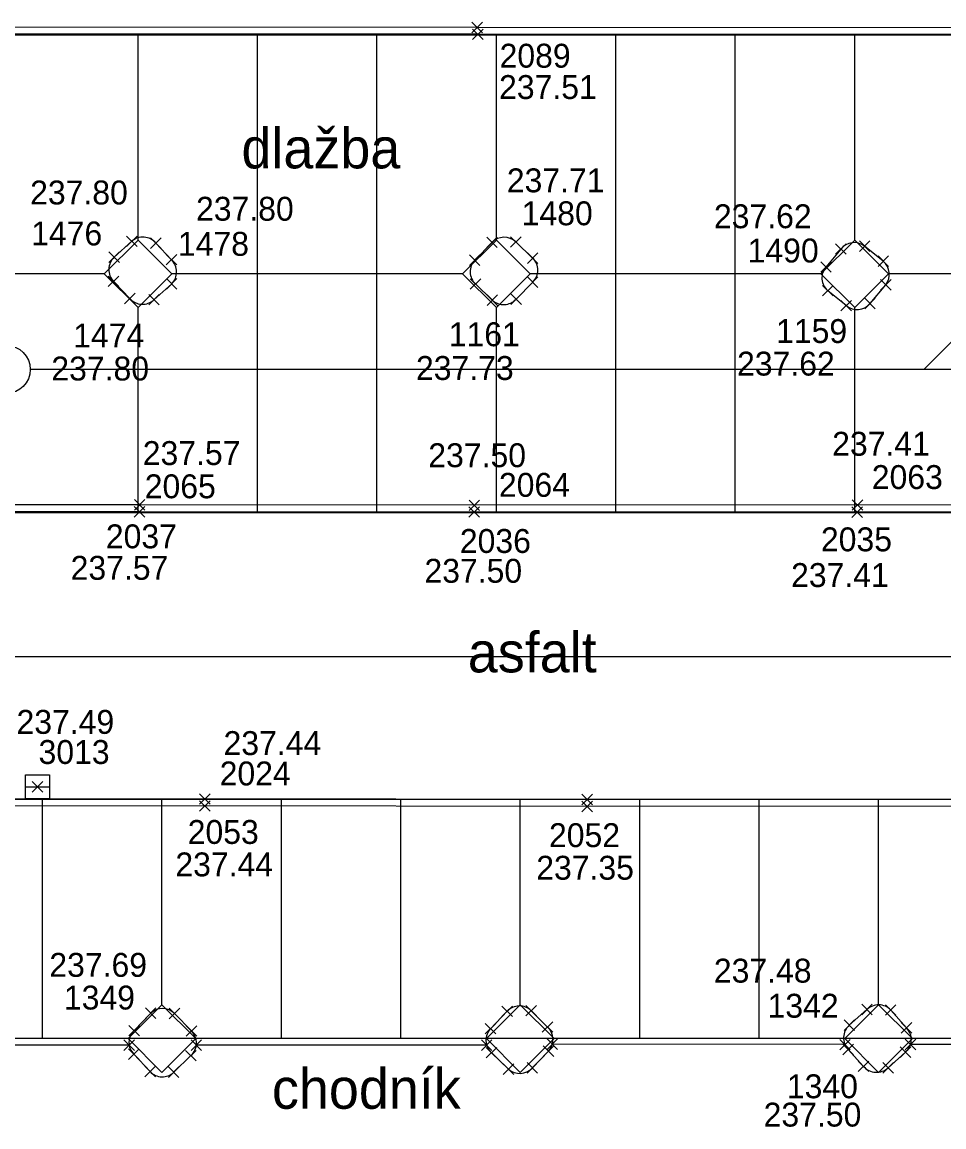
# Model space of a CAD drawing. Extents: x -264165 to -263733, y -1242319 to -1242245.
# Drawn here: x -263870.5 to -263851.2, y -1242299.83 to -1242276.71 of the extents above; entities that cross this region are included whole.
import ezdxf

# ---------------------------------------------------------------- set-up
doc = ezdxf.new("R2010")
doc.units = 0
for name, color, linetype in [('KFA_BOD_CISLO', 7, 'Continuous'), ('KFA_BOD_SYMBOL', 7, 'Continuous'), ('KFA_BOD_VYSKA', 7, 'Continuous'), ('KFA_SO_20-2_OBRUBNIKY_DOLNA_HRANA', 7, 'Continuous'), ('KFA_SO_20-2_OBRUBNIKY_HORNA_HRANA', 7, 'Continuous'), ('KFA_UV_BOD_CISLO', 7, 'Continuous'), ('KFA_UV_BOD_SYMBOL', 7, 'Continuous'), ('KFA_UV_BOD_VYSKA', 7, 'Continuous'), ('POPIS', 7, 'Continuous'), ('PROJEKT_OBRUBNIKY_KOMUNIKACIE', 7, 'Continuous'), ('PROJEKT_TDZ_VODOROVNE', 7, 'Continuous'), ('SITUACIA_DSP_2D', 7, 'Continuous'), ('ULICNA_VPUST_POKLOP', 7, 'Continuous')]:
    doc.layers.add(name, color=color, linetype=linetype)

msp = doc.modelspace()

# ---------------------------------------------------------------- linework, layer by layer
at = {"layer": 'KFA_BOD_SYMBOL'}
for p, q in [((-263861.079, -1242276.936), (-263860.858, -1242276.715)), ((-263860.858, -1242276.936), (-263861.079, -1242276.715)), ((-263861.068, -1242277.079), (-263860.847, -1242276.859)), ((-263860.847, -1242277.079), (-263861.068, -1242276.859)), ((-263868.311, -1242281.411), (-263868.09, -1242281.191)), ((-263868.09, -1242281.411), (-263868.311, -1242281.191)), ((-263860.272, -1242281.426), (-263860.051, -1242281.204)), ((-263860.051, -1242281.426), (-263860.272, -1242281.204)), ((-263867.806, -1242281.448), (-263867.584, -1242281.227)), ((-263867.584, -1242281.448), (-263867.806, -1242281.227)), ((-263860.769, -1242281.434), (-263860.549, -1242281.214)), ((-263860.549, -1242281.434), (-263860.769, -1242281.214)), ((-263853.469, -1242281.573), (-263853.247, -1242281.353)), ((-263853.247, -1242281.573), (-263853.469, -1242281.353)), ((-263852.971, -1242281.514), (-263852.75, -1242281.292)), ((-263852.75, -1242281.514), (-263852.971, -1242281.292)), ((-263868.677, -1242281.742), (-263868.456, -1242281.522)), ((-263868.456, -1242281.742), (-263868.677, -1242281.522)), ((-263867.48, -1242281.796), (-263867.258, -1242281.576)), ((-263867.258, -1242281.796), (-263867.48, -1242281.576)), ((-263861.133, -1242281.806), (-263860.911, -1242281.585)), ((-263860.911, -1242281.806), (-263861.133, -1242281.585)), ((-263859.92, -1242281.762), (-263859.698, -1242281.542)), ((-263859.698, -1242281.762), (-263859.92, -1242281.542)), ((-263852.579, -1242281.829), (-263852.358, -1242281.607)), ((-263852.358, -1242281.829), (-263852.579, -1242281.607)), ((-263853.78, -1242281.95), (-263853.559, -1242281.728)), ((-263853.559, -1242281.95), (-263853.78, -1242281.728)), ((-263868.691, -1242282.249), (-263868.47, -1242282.029)), ((-263868.47, -1242282.249), (-263868.691, -1242282.029)), ((-263867.475, -1242282.302), (-263867.253, -1242282.08)), ((-263867.253, -1242282.302), (-263867.475, -1242282.08)), ((-263861.116, -1242282.303), (-263860.894, -1242282.083)), ((-263860.894, -1242282.303), (-263861.116, -1242282.083)), ((-263859.919, -1242282.265), (-263859.698, -1242282.045)), ((-263859.698, -1242282.265), (-263859.919, -1242282.045)), ((-263852.529, -1242282.323), (-263852.307, -1242282.102)), ((-263852.307, -1242282.323), (-263852.529, -1242282.102)), ((-263853.743, -1242282.444), (-263853.522, -1242282.224)), ((-263853.522, -1242282.444), (-263853.743, -1242282.224)), ((-263868.351, -1242282.61), (-263868.129, -1242282.389)), ((-263868.129, -1242282.61), (-263868.351, -1242282.389)), ((-263867.845, -1242282.633), (-263867.625, -1242282.413)), ((-263867.625, -1242282.633), (-263867.845, -1242282.413)), ((-263860.764, -1242282.641), (-263860.543, -1242282.421)), ((-263860.543, -1242282.641), (-263860.764, -1242282.421)), ((-263860.264, -1242282.622), (-263860.043, -1242282.4)), ((-263860.043, -1242282.622), (-263860.264, -1242282.4)), ((-263853.356, -1242282.758), (-263853.135, -1242282.536)), ((-263853.135, -1242282.758), (-263853.356, -1242282.536)), ((-263852.859, -1242282.713), (-263852.638, -1242282.492)), ((-263852.638, -1242282.713), (-263852.859, -1242282.492)), ((-263868.144, -1242286.927), (-263867.924, -1242286.705)), ((-263867.924, -1242286.927), (-263868.144, -1242286.705)), ((-263861.141, -1242286.936), (-263860.92, -1242286.715)), ((-263860.92, -1242286.936), (-263861.141, -1242286.715)), ((-263853.122, -1242286.928), (-263852.901, -1242286.708)), ((-263852.901, -1242286.928), (-263853.122, -1242286.708)), ((-263868.148, -1242287.07), (-263867.927, -1242286.85)), ((-263867.927, -1242287.07), (-263868.148, -1242286.85)), ((-263861.143, -1242287.076), (-263860.921, -1242286.856)), ((-263860.921, -1242287.076), (-263861.143, -1242286.856)), ((-263853.128, -1242287.079), (-263852.906, -1242286.857)), ((-263852.906, -1242287.079), (-263853.128, -1242286.857)), ((-263866.781, -1242293.079), (-263866.56, -1242292.859)), ((-263866.56, -1242293.079), (-263866.781, -1242292.859)), ((-263858.78, -1242293.089), (-263858.559, -1242292.867)), ((-263858.559, -1242293.089), (-263858.78, -1242292.867)), ((-263866.779, -1242293.225), (-263866.557, -1242293.005)), ((-263866.557, -1242293.225), (-263866.779, -1242293.005)), ((-263858.778, -1242293.235), (-263858.557, -1242293.014)), ((-263858.557, -1242293.235), (-263858.778, -1242293.014)), ((-263867.914, -1242297.561), (-263867.693, -1242297.34)), ((-263867.693, -1242297.561), (-263867.914, -1242297.34)), ((-263867.414, -1242297.569), (-263867.193, -1242297.349)), ((-263867.193, -1242297.569), (-263867.414, -1242297.349)), ((-263860.454, -1242297.522), (-263860.233, -1242297.301)), ((-263860.233, -1242297.522), (-263860.454, -1242297.301)), ((-263859.949, -1242297.509), (-263859.728, -1242297.289)), ((-263859.728, -1242297.509), (-263859.949, -1242297.289)), ((-263852.922, -1242297.487), (-263852.701, -1242297.265)), ((-263852.701, -1242297.487), (-263852.922, -1242297.265)), ((-263852.425, -1242297.495), (-263852.204, -1242297.275)), ((-263852.204, -1242297.495), (-263852.425, -1242297.275)), ((-263853.291, -1242297.813), (-263853.07, -1242297.593)), ((-263853.07, -1242297.813), (-263853.291, -1242297.593)), ((-263868.262, -1242297.927), (-263868.041, -1242297.705)), ((-263868.041, -1242297.927), (-263868.262, -1242297.705)), ((-263867.062, -1242297.934), (-263866.84, -1242297.713)), ((-263866.84, -1242297.934), (-263867.062, -1242297.713)), ((-263860.8, -1242297.886), (-263860.579, -1242297.664)), ((-263860.579, -1242297.886), (-263860.8, -1242297.664)), ((-263859.611, -1242297.85), (-263859.389, -1242297.63)), ((-263859.389, -1242297.85), (-263859.611, -1242297.63)), ((-263852.095, -1242297.87), (-263851.873, -1242297.649)), ((-263851.873, -1242297.87), (-263852.095, -1242297.649)), ((-263868.366, -1242298.228), (-263868.144, -1242298.008)), ((-263868.144, -1242298.228), (-263868.366, -1242298.008)), ((-263866.959, -1242298.231), (-263866.738, -1242298.011)), ((-263866.738, -1242298.231), (-263866.959, -1242298.011)), ((-263860.883, -1242298.228), (-263860.661, -1242298.008)), ((-263860.661, -1242298.228), (-263860.883, -1242298.008)), ((-263859.508, -1242298.208), (-263859.287, -1242297.988)), ((-263859.287, -1242298.208), (-263859.508, -1242297.988)), ((-263853.382, -1242298.218), (-263853.16, -1242297.998)), ((-263853.16, -1242298.218), (-263853.382, -1242297.998)), ((-263852.012, -1242298.218), (-263851.791, -1242297.997)), ((-263851.791, -1242298.218), (-263852.012, -1242297.997)), ((-263868.268, -1242298.417), (-263868.046, -1242298.197)), ((-263868.046, -1242298.417), (-263868.268, -1242298.197)), ((-263867.073, -1242298.45), (-263866.852, -1242298.228)), ((-263866.852, -1242298.45), (-263867.073, -1242298.228)), ((-263860.781, -1242298.387), (-263860.56, -1242298.167)), ((-263860.56, -1242298.387), (-263860.781, -1242298.167)), ((-263859.59, -1242298.356), (-263859.368, -1242298.134)), ((-263859.368, -1242298.356), (-263859.59, -1242298.134)), ((-263853.315, -1242298.319), (-263853.094, -1242298.097)), ((-263853.094, -1242298.319), (-263853.315, -1242298.097)), ((-263852.117, -1242298.377), (-263851.896, -1242298.156)), ((-263851.896, -1242298.377), (-263852.117, -1242298.156)), ((-263860.427, -1242298.732), (-263860.205, -1242298.512)), ((-263860.205, -1242298.732), (-263860.427, -1242298.512)), ((-263859.925, -1242298.707), (-263859.704, -1242298.485)), ((-263859.704, -1242298.707), (-263859.925, -1242298.485)), ((-263852.995, -1242298.674), (-263852.774, -1242298.453)), ((-263852.774, -1242298.674), (-263852.995, -1242298.453)), ((-263852.478, -1242298.703), (-263852.257, -1242298.481)), ((-263852.257, -1242298.703), (-263852.478, -1242298.481)), ((-263867.927, -1242298.784), (-263867.705, -1242298.562)), ((-263867.705, -1242298.784), (-263867.927, -1242298.562)), ((-263867.432, -1242298.798), (-263867.212, -1242298.576)), ((-263867.212, -1242298.798), (-263867.432, -1242298.576))]:
    msp.add_line(p, q, dxfattribs=at)
at = {"layer": 'KFA_SO_20-2_OBRUBNIKY_DOLNA_HRANA'}
for points in [[(-263816.727, -1242276.824), (-263824.896, -1242276.832), (-263841.932, -1242276.838), (-263860.969, -1242276.825), (-263872.991, -1242276.822), (-263881, -1242276.818), (-263897.019, -1242276.831), (-263905.035, -1242276.846), (-263913.057, -1242276.848), (-263917.557, -1242276.899)], [(-263817.074, -1242276.98), (-263824.904, -1242276.976), (-263831.918, -1242276.976), (-263841.931, -1242276.979), (-263850.949, -1242276.976), (-263860.958, -1242276.969), (-263872.991, -1242276.965), (-263880.996, -1242276.964), (-263889.006, -1242276.968), (-263897.017, -1242276.976), (-263905.035, -1242276.99), (-263913.048, -1242276.994), (-263917.092, -1242277.009)], [(-263819.103, -1242286.786), (-263819.439, -1242286.959), (-263828.996, -1242286.962), (-263838.005, -1242286.965), (-263845.009, -1242286.967), (-263853.017, -1242286.968), (-263861.032, -1242286.966), (-263868.037, -1242286.96), (-263877.037, -1242286.952), (-263886.053, -1242286.951), (-263895.068, -1242286.953), (-263904.067, -1242286.955), (-263910.084, -1242286.961), (-263917.346, -1242286.958)], [(-263819.419, -1242286.819), (-263828.995, -1242286.822), (-263838.007, -1242286.821), (-263845.022, -1242286.826), (-263853.012, -1242286.818), (-263861.03, -1242286.825), (-263868.034, -1242286.816), (-263877.043, -1242286.812), (-263886.05, -1242286.81), (-263895.064, -1242286.807), (-263904.07, -1242286.816), (-263910.08, -1242286.821), (-263917.062, -1242286.824)], [(-263817.492, -1242292.982), (-263829.632, -1242292.973), (-263839.651, -1242292.963), (-263849.653, -1242292.97), (-263858.67, -1242292.978), (-263866.671, -1242292.969), (-263877.683, -1242292.971), (-263887.693, -1242292.984), (-263898.705, -1242293.002), (-263909.705, -1242293.003), (-263917.41, -1242292.997)], [(-263817.431, -1242293.129), (-263829.63, -1242293.121), (-263839.649, -1242293.107), (-263849.656, -1242293.117), (-263858.667, -1242293.124), (-263866.668, -1242293.115), (-263877.682, -1242293.116), (-263887.695, -1242293.128), (-263898.705, -1242293.142), (-263909.706, -1242293.151), (-263917.057, -1242293.143)]]:
    msp.add_lwpolyline(points, dxfattribs=at)
at = {"layer": 'KFA_SO_20-2_OBRUBNIKY_HORNA_HRANA'}
for p, q in [((-263868.567, -1242281.632), (-263868.2, -1242281.301)), ((-263867.695, -1242281.337), (-263867.369, -1242281.686)), ((-263861.022, -1242281.695), (-263860.659, -1242281.324)), ((-263860.161, -1242281.315), (-263859.809, -1242281.652)), ((-263852.469, -1242281.718), (-263852.861, -1242281.403)), ((-263853.358, -1242281.463), (-263853.67, -1242281.839)), ((-263868.58, -1242282.139), (-263868.24, -1242282.499)), ((-263867.364, -1242282.191), (-263867.735, -1242282.523)), ((-263860.654, -1242282.531), (-263861.005, -1242282.193)), ((-263859.808, -1242282.155), (-263860.154, -1242282.511)), ((-263853.246, -1242282.647), (-263853.633, -1242282.334)), ((-263852.748, -1242282.602), (-263852.418, -1242282.212)), ((-263853.181, -1242297.703), (-263852.812, -1242297.376)), ((-263852.314, -1242297.385), (-263851.984, -1242297.759)), ((-263867.803, -1242297.45), (-263868.151, -1242297.816)), ((-263866.951, -1242297.823), (-263867.303, -1242297.459)), ((-263860.689, -1242297.775), (-263860.344, -1242297.411)), ((-263859.839, -1242297.399), (-263859.5, -1242297.74)), ((-263868.255, -1242298.118), (-263874.363, -1242298.116)), ((-263868.157, -1242298.307), (-263867.816, -1242298.673)), ((-263860.772, -1242298.118), (-263866.849, -1242298.121)), ((-263860.316, -1242298.622), (-263860.671, -1242298.277)), ((-263859.479, -1242298.245), (-263859.814, -1242298.596)), ((-263853.271, -1242298.108), (-263859.398, -1242298.098)), ((-263852.884, -1242298.563), (-263853.204, -1242298.208)), ((-263852.367, -1242298.592), (-263852.007, -1242298.266)), ((-263845.781, -1242298.106), (-263851.901, -1242298.107)), ((-263866.963, -1242298.339), (-263867.322, -1242298.687))]:
    msp.add_line(p, q, dxfattribs=at)
for centre, major_axis, ratio, start_param, end_param in [((-263867.965, -1242281.57), (-0.352, -0.062), 0.999702, 3.679514, 5.255314), ((-263860.406, -1242281.573), (-0.331, -0.13), 0.999188, 3.579337, 5.132842), ((-263853.079, -1242281.685), (-0.357, -0.002), 0.998601, 4.048789, 5.603133), ((-263868.323, -1242281.892), (0.053, -0.353), 0.999424, 3.746783, 5.32766), ((-263860.049, -1242281.904), (0.135, 0.321), 0.999948, 4.303653, 5.919728), ((-263867.616, -1242281.941), (0.342, 0.096), 0.99983, 5.22782, 6.810775), ((-263860.769, -1242281.936), (0.104, -0.333), 0.999545, 3.648853, 5.237105), ((-263853.404, -1242282.068), (0.129, -0.326), 0.99917, 3.62549, 5.196843), ((-263852.7, -1242281.991), (-0.141, 0.329), 0.999169, 3.645056, 5.17794), ((-263867.976, -1242282.272), (0.156, -0.311), 0.999742, 4.957365, 6.582649), ((-263860.414, -1242282.272), (0.329, -0.13), 0.99878, 4.341802, 5.91614), ((-263853.02, -1242282.374), (0.349, -0.064), 0.999305, 4.20114, 5.766647), ((-263867.558, -1242297.713), (-0.354, -0.063), 0.999142, 3.750126, 5.28599), ((-263860.086, -1242297.654), (-0.351, 0.053), 0.999406, 4.093364, 5.677882), ((-263852.567, -1242297.624), (-0.036, -0.346), 0.999968, 2.431773, 4.02502), ((-263867.921, -1242298.064), (-0.224, 0.253), 0.999784, 0.022173, 1.647004), ((-263867.201, -1242298.075), (0.132, 0.33), 0.999753, 4.256123, 5.880954), ((-263860.437, -1242298.017), (-0.049, -0.346), 0.999426, 4.087404, 5.6918), ((-263859.743, -1242298.003), (-0.015, 0.358), 0.999575, 3.929578, 5.4952), ((-263852.952, -1242297.967), (0.247, -0.247), 0.999566, 3.071997, 4.690526), ((-263852.231, -1242298.002), (0.215, 0.272), 0.999858, 4.514031, 6.157491), ((-263867.562, -1242298.438), (0.341, 0.054), 0.999465, 3.729392, 5.322172), ((-263860.078, -1242298.353), (0.244, 0.263), 0.999963, 3.166099, 4.717299), ((-263852.612, -1242298.329), (0.264, -0.244), 0.999442, 4.59699, 6.205917)]:
    msp.add_ellipse(centre, major_axis=major_axis, ratio=ratio, start_param=start_param, end_param=end_param, dxfattribs=at)
at = {"layer": 'KFA_UV_BOD_SYMBOL'}
for p, q in [((-263870.284, -1242292.826), (-263870.062, -1242292.605)), ((-263870.062, -1242292.826), (-263870.284, -1242292.605))]:
    msp.add_line(p, q, dxfattribs=at)
at = {"layer": 'PROJEKT_OBRUBNIKY_KOMUNIKACIE'}
for p, q in [((-263917.08, -1242276.982), (-263817.068, -1242276.982)), ((-263819.568, -1242286.982), (-263917.08, -1242286.982)), ((-263817.19, -1242292.982), (-263917.08, -1242292.982)), ((-263815.601, -1242297.982), (-263917.08, -1242297.982))]:
    msp.add_line(p, q, dxfattribs=at)
for points in [[(-263868.068, -1242281.275), (-263867.361, -1242281.982), (-263868.068, -1242282.689), (-263868.775, -1242281.982), (-263868.068, -1242281.275)], [(-263860.568, -1242281.275), (-263859.861, -1242281.982), (-263860.568, -1242282.689), (-263861.275, -1242281.982), (-263860.568, -1242281.275)], [(-263853.068, -1242281.275), (-263852.361, -1242281.982), (-263853.068, -1242282.689), (-263853.775, -1242281.982), (-263853.068, -1242281.275)], [(-263867.568, -1242297.275), (-263866.861, -1242297.982), (-263867.568, -1242298.689), (-263868.275, -1242297.982), (-263867.568, -1242297.275)], [(-263860.068, -1242297.275), (-263859.361, -1242297.982), (-263860.068, -1242298.689), (-263860.775, -1242297.982), (-263860.068, -1242297.275)], [(-263852.568, -1242297.275), (-263851.861, -1242297.982), (-263852.568, -1242298.689), (-263853.275, -1242297.982), (-263852.568, -1242297.275)]]:
    msp.add_lwpolyline(points, dxfattribs=at)
at = {"layer": 'PROJEKT_TDZ_VODOROVNE'}
for p, q in [((-263868.068, -1242281.275), (-263868.068, -1242276.982)), ((-263865.568, -1242281.982), (-263865.568, -1242276.982)), ((-263863.068, -1242281.982), (-263863.068, -1242276.982)), ((-263860.568, -1242281.275), (-263860.568, -1242276.982)), ((-263858.068, -1242281.982), (-263858.068, -1242276.982)), ((-263855.568, -1242281.982), (-263855.568, -1242276.982)), ((-263853.068, -1242281.275), (-263853.068, -1242276.982)), ((-263868.775, -1242281.982), (-263874.861, -1242281.982)), ((-263861.275, -1242281.982), (-263867.361, -1242281.982)), ((-263865.568, -1242286.982), (-263865.568, -1242281.982)), ((-263863.068, -1242286.982), (-263863.068, -1242281.982)), ((-263853.775, -1242281.982), (-263859.861, -1242281.982)), ((-263858.068, -1242286.982), (-263858.068, -1242281.982)), ((-263855.568, -1242286.982), (-263855.568, -1242281.982)), ((-263846.275, -1242281.982), (-263852.361, -1242281.982)), ((-263868.068, -1242286.982), (-263868.068, -1242282.689)), ((-263860.568, -1242286.982), (-263860.568, -1242282.689)), ((-263853.068, -1242286.982), (-263853.068, -1242282.689)), ((-263819.531, -1242289.994), (-263917.477, -1242289.994)), ((-263870.068, -1242297.982), (-263870.068, -1242292.982)), ((-263867.568, -1242297.275), (-263867.568, -1242292.982)), ((-263865.068, -1242297.982), (-263865.068, -1242292.982)), ((-263862.568, -1242297.982), (-263862.568, -1242292.982)), ((-263860.068, -1242297.275), (-263860.068, -1242292.982)), ((-263857.568, -1242297.982), (-263857.568, -1242292.982)), ((-263855.068, -1242297.982), (-263855.068, -1242292.982)), ((-263852.568, -1242297.275), (-263852.568, -1242292.982))]:
    msp.add_line(p, q, dxfattribs=at)
at = {"layer": 'SITUACIA_DSP_2D'}
for p, q in [((-263850.824, -1242283.187), (-263851.619, -1242283.982)), ((-263817.941, -1242283.982), (-263870.324, -1242283.982)), ((-263817.941, -1242283.982), (-263870.324, -1242283.982)), ((-263815.601, -1242297.982), (-263917.08, -1242297.982))]:
    msp.add_line(p, q, dxfattribs=at)
for points in [[(-263868.068, -1242281.275), (-263867.361, -1242281.982), (-263868.068, -1242282.689), (-263868.775, -1242281.982)], [(-263860.568, -1242281.275), (-263859.861, -1242281.982), (-263860.568, -1242282.689), (-263861.275, -1242281.982)], [(-263853.068, -1242281.275), (-263852.361, -1242281.982), (-263853.068, -1242282.689), (-263853.775, -1242281.982)], [(-263867.568, -1242297.275), (-263866.861, -1242297.982), (-263867.568, -1242298.689), (-263868.275, -1242297.982)], [(-263860.068, -1242297.275), (-263859.361, -1242297.982), (-263860.068, -1242298.689), (-263860.775, -1242297.982)], [(-263852.568, -1242297.275), (-263851.861, -1242297.982), (-263852.568, -1242298.689), (-263853.275, -1242297.982)]]:
    msp.add_lwpolyline(points, close=True, dxfattribs=at)
msp.add_circle((-263870.824, -1242283.982), 0.5, dxfattribs=at)
at = {"layer": 'ULICNA_VPUST_POKLOP'}
msp.add_line((-263870.173, -1242292.715), (-263870.173, -1242292.715), dxfattribs=at)
msp.add_lwpolyline([(-263870.423, -1242292.715), (-263870.423, -1242292.465), (-263869.923, -1242292.465), (-263869.923, -1242292.965), (-263870.423, -1242292.965), (-263870.423, -1242292.715), (-263869.923, -1242292.715)], dxfattribs=at)

# ---------------------------------------------------------------- texts
at = {"layer": 'KFA_BOD_CISLO'}
for s, p in [('2089', (-263860.501, -1242277.668)), ('1480', (-263860.039, -1242280.965)), ('1476', (-263870.306, -1242281.387)), ('1478', (-263867.234, -1242281.604)), ('1490', (-263855.309, -1242281.744)), ('1474', (-263869.426, -1242283.522)), ('1161', (-263861.565, -1242283.496)), ('1159', (-263854.714, -1242283.429)), ('2063', (-263852.711, -1242286.484)), ('2065', (-263867.928, -1242286.677)), ('2064', (-263860.515, -1242286.647)), ('2037', (-263868.742, -1242287.724)), ('2036', (-263861.333, -1242287.821)), ('2035', (-263853.775, -1242287.787)), ('2024', (-263866.36, -1242292.685)), ('2053', (-263867.029, -1242293.909)), ('2052', (-263859.467, -1242293.976)), ('1349', (-263869.62, -1242297.374)), ('1342', (-263854.892, -1242297.545)), ('1340', (-263854.488, -1242299.23))]:
    msp.add_text(s, height=0.5, dxfattribs=at).set_placement(p)
at = {"layer": 'KFA_BOD_VYSKA'}
for s, p in [('237.51', (-263860.512, -1242278.324)), ('237.71', (-263860.35, -1242280.276)), ('237.80', (-263870.327, -1242280.53)), ('237.80', (-263866.855, -1242280.87)), ('237.62', (-263856.014, -1242281.027)), ('237.80', (-263869.883, -1242284.213)), ('237.73', (-263862.251, -1242284.202)), ('237.62', (-263855.531, -1242284.11)), ('237.41', (-263853.54, -1242285.787)), ('237.57', (-263867.97, -1242285.982)), ('237.50', (-263861.993, -1242286.027)), ('237.57', (-263869.479, -1242288.383)), ('237.50', (-263862.074, -1242288.445)), ('237.41', (-263854.4, -1242288.534)), ('237.44', (-263866.279, -1242292.05)), ('237.44', (-263867.287, -1242294.588)), ('237.35', (-263859.734, -1242294.658)), ('237.69', (-263869.925, -1242296.69)), ('237.48', (-263856.016, -1242296.811)), ('237.50', (-263854.974, -1242299.823))]:
    msp.add_text(s, height=0.5, dxfattribs=at).set_placement(p)
at = {"layer": 'KFA_UV_BOD_CISLO'}
msp.add_text('3013', height=0.5, dxfattribs=at).set_placement((-263870.151, -1242292.236))
at = {"layer": 'KFA_UV_BOD_VYSKA'}
msp.add_text('237.49', height=0.5, dxfattribs=at).set_placement((-263870.612, -1242291.606))
at = {"layer": 'POPIS'}
for s, p in [('dlažba', (-263865.904, -1242279.775)), ('asfalt', (-263861.166, -1242290.32)), ('chodník', (-263865.266, -1242299.451))]:
    msp.add_text(s, height=0.8438, dxfattribs=at).set_placement(p)

doc.saveas('drawing.dxf')
